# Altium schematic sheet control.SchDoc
size A4
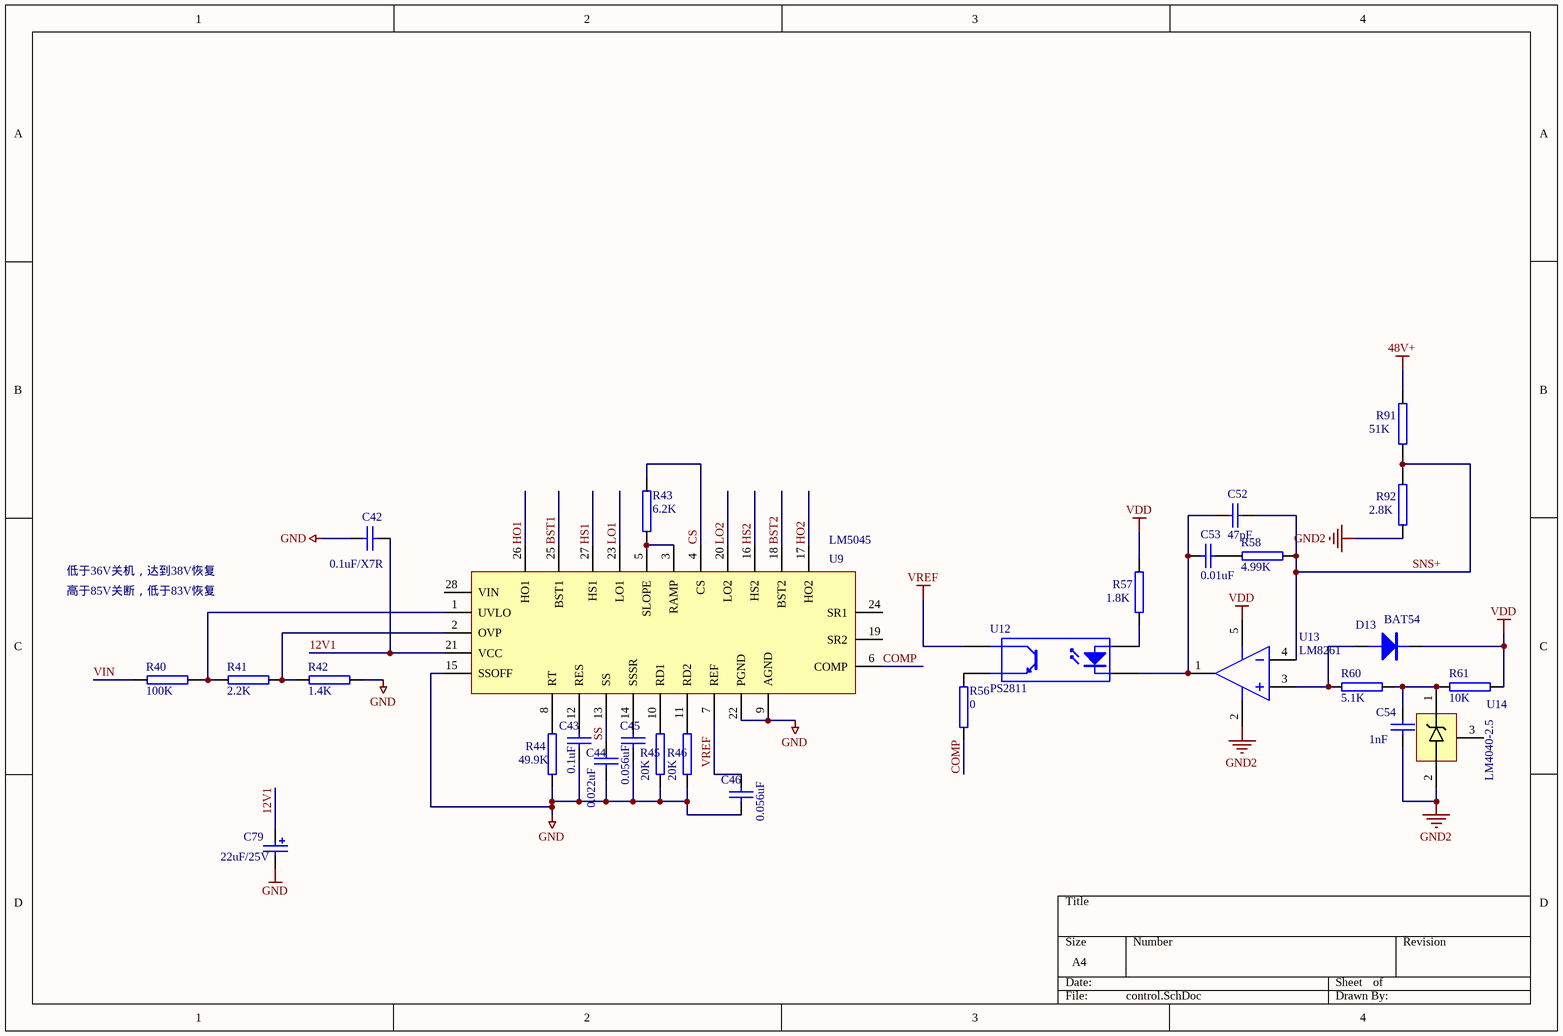
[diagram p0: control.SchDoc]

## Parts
C42  0.1uF/X7R  [0805-C]
C43  0.1uF  [0805-C]
C44  0.022uF  [0805-C]
C45  0.056uF  [0805-C]
C46  0.056uF  [0805-C]
C52  47pF  [0805-C]
C53  0.01uF  [0805-C]
C54  1nF  [0805-C]
C79  22uF/25V  [CD2.5/6.3]
D13  BAT54  [SOT-23]
R40  100K  [0805]
R41  2.2K  [0805]
R42  1.4K  [0805]
R43  6.2K  [0805]
R44  49.9K  [0805]
R45  20K  [0805]
R46  20K  [0805]
R56  0  [0805]
R57  1.8K  [0805]
R58  4.99K  [0805]
R60  5.1K  [0805]
R61  10K  [0805]
R91  51K  [0805]
R92  2.8K  [0805]
U9  LM5045  [TSSOP28]
U12  PS2811  [PS2811]
U13  LM8261  [LM8261]
U14  LM4040-2.5  [SOT-23]

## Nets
48V+: R91.1
GND: C42.1 C43.1 C44.1 C45.1 C46.1 C79.2 R42.1 R44.2 R45.2 R46.2 U9.9(AGND) U9.15(SSOFF) U9.22(PGND)
GND2: C54.2 R92.2 U13.2(GND) U14.2
VDD: D13.3(K) R57.1 R61.1 U13.5(15V1)
VREF: C46.2 U9.7(REF) U12.4(C)
12V1: C42.2 C79.1 U9.21(VCC)
BST1: U9.25(BST1)
BST2: U9.18(BST2)
COMP: R56.1 U9.6(COMP)
CS: R43.1 U9.4(CS)
HO1: U9.26(HO1)
HO2: U9.17(HO2)
HS1: U9.27(HS1)
HS2: U9.16(HS2)
LO1: U9.23(LO1)
LO2: U9.20(LO2)
SNS+: C52.1 R58.2 R91.2 R92.1 U13.4(IN-)
SS: C44.2 U9.13(SS)
VIN: R40.1
NetC43_2: C43.2 U9.12(RES)
NetC45_2: C45.2 U9.14(SSSR)
NetC52_2: C52.2 C53.2 U12.2(K) U13.1(OUT)
NetC53_1: C53.1 R58.1
NetC54_1: C54.1 R60.2 R61.2 U14.1
NetD13_1: D13.1(A) R60.1 U13.3(IN+)
NetR40_2: R40.2 R41.2 U9.1(UVLO)
NetR41_1: R41.1 R42.2 U9.2(OVP)
NetR43_2: R43.2 U9.3(RAMP) U9.5(SLOPE)
NetR44_1: R44.1 U9.8(RT)
NetR45_1: R45.1 U9.10(RD1)
NetR46_1: R46.1 U9.11(RD2)
NetR56_2: R56.2 U12.3(E)
NetR57_2: R57.2 U12.1(A)

Not connected (* = marked no-connect by the designer): U9 19(SR2) 24(SR1) 28(VIN); U14 3

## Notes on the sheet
- 低于36V关机，达到38V恢复
- 高于85V关断，低于83V恢复

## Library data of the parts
C42-C46 C52 C53 = C
C54 = CAP: Capacitor
C79 = C1
D13 = MMBD4148
R40-R46 R56-R58 R60 R61 R91 R92 = 205886
U12 = OPTOISO1: Optoisolator
U14 = LM4040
